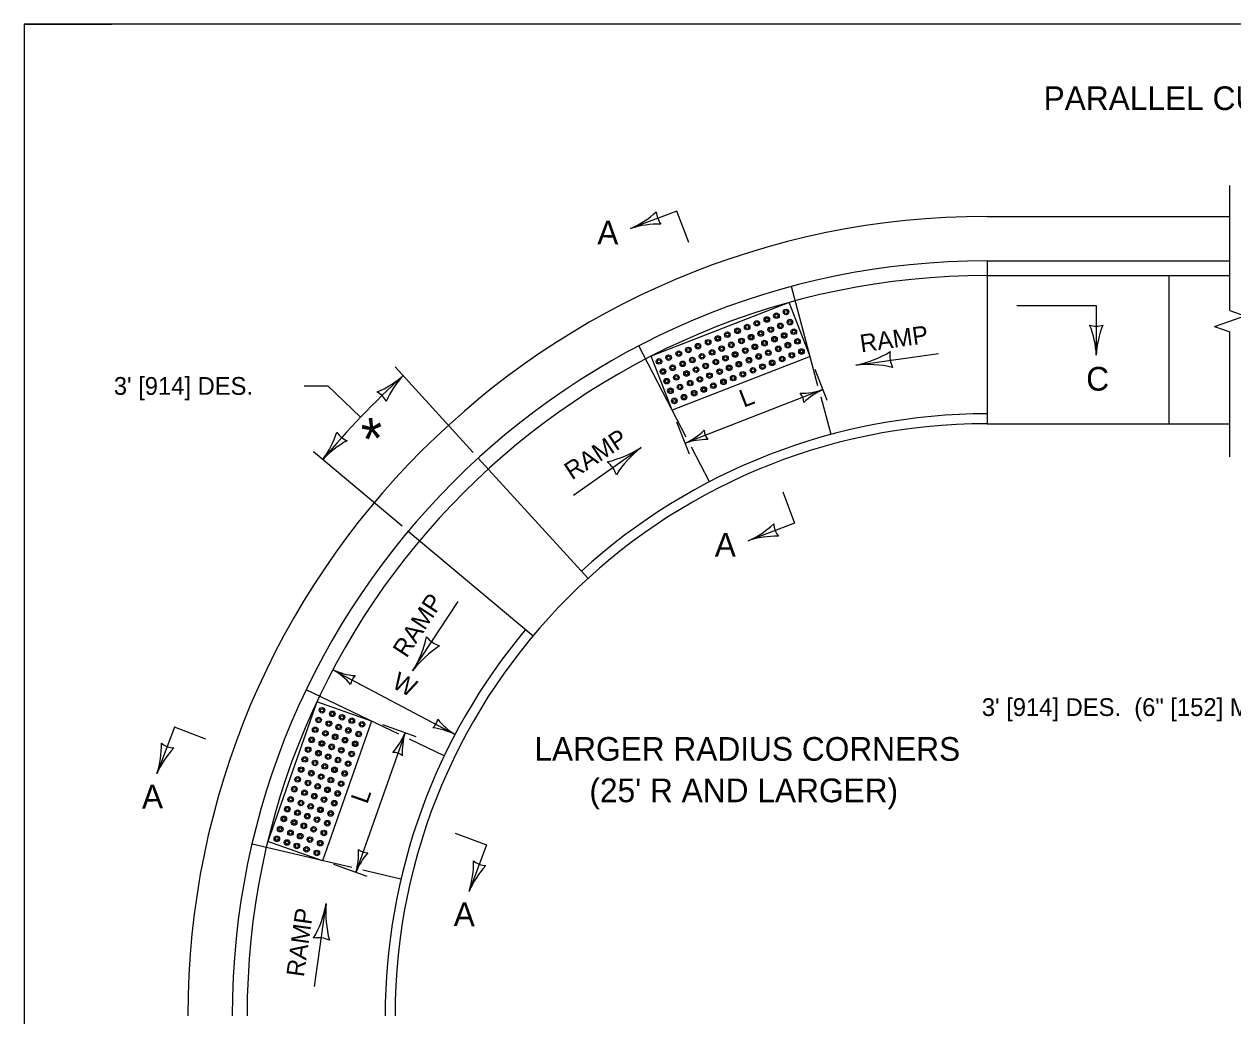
# Model space of a CAD drawing. Extents: x 49991.4 to 50021, y 49987.6 to 50011.4.
# Drawn here: x 50000.336 to 50004.419, y 50007.914 to 50011.263 of the extents above; entities that cross this region are included whole.
import ezdxf

# ---------------------------------------------------------------- set-up
doc = ezdxf.new("R2010")
doc.units = 0
for name, color, linetype in [('Level 1', 7, 'Continuous'), ('Level 2', 7, 'Continuous'), ('Level 3', 7, 'Continuous'), ('Level 6', 7, 'Continuous'), ('Level 8', 7, 'Continuous'), ('P_Dimensions_Styles_Eng', 7, 'Continuous')]:
    doc.layers.add(name, color=color, linetype=linetype)

msp = doc.modelspace()

# ---------------------------------------------------------------- linework, layer by layer
at = {"layer": 'Level 1'}
for p, q in [((50003.5886, 50010.6135), (50004.4081, 50010.6135)), ((50003.5886, 50010.4635), (50004.4081, 50010.4635)), ((50003.5888, 50010.4635), (50003.5888, 50009.9135)), ((50003.5886, 50010.4135), (50004.4081, 50010.4135)), ((50004.2021, 50010.4135), (50004.2021, 50009.9135)), ((50003.0173, 50010.0415), (50002.9275, 50010.3763)), ((50002.5719, 50009.8685), (50002.412, 50010.1759)), ((50002.9909, 50010.1401), (50002.5249, 50009.9589)), ((50003.0614, 50009.8773), (50003.0277, 50010.0027)), ((50003.5886, 50009.9135), (50004.4081, 50009.9135)), ((50001.8698, 50009.7972), (50002.2405, 50009.3909)), ((50002.6504, 50009.7175), (50002.5895, 50009.8346)), ((50001.6332, 50009.5503), (50002.0549, 50009.1973)), ((50001.6013, 50008.8652), (50001.2887, 50009.015)), ((50001.5093, 50008.9093), (50001.3435, 50008.4376)), ((50001.7547, 50008.7918), (50001.6375, 50008.8479)), ((50001.4427, 50008.4144), (50001.1053, 50008.4932)), ((50001.6085, 50008.3757), (50001.4798, 50008.4058))]:
    msp.add_line(p, q, dxfattribs=at)
msp.add_lwpolyline([(50008.6146, 50011.2628), (50000.3356, 50011.2628), (50000.3356, 50000.0624), (50008.6146, 50000.0624)], close=True, dxfattribs=at)
for points in [[(50000.3356, 50011.2628), (50000.3356, 50000.0624)], [(50008.6146, 50011.2628), (50000.3356, 50011.2628)]]:
    msp.add_lwpolyline(points, dxfattribs=at)
for radius, start, end in [(2.7, 89.9972, 179.9963), (2.55, 89.9972, 179.9963), (2.5, 89.9972, 179.9963), (2.0333, 89.9972, 132.3771), (2, 89.9972, 179.9963), (2.0333, 140.0675, 179.9963)]:
    msp.add_arc((50003.5885, 50007.9135), radius, start, end, dxfattribs=at)
at = {"layer": 'Level 2'}
for centre in [(50002.6723, 50010.1218), (50002.7048, 50010.1345), (50002.7373, 50010.1471), (50001.3273, 50008.6885), (50001.3389, 50008.7214), (50001.3157, 50008.6556)]:
    msp.add_circle(centre, 0.00945, dxfattribs=at)
at = {"layer": 'Level 3'}
for p, q in [((50000.3356, 50011.2628), (50000.6313, 50011.2628)), ((50002.9199, 50010.3224), (50002.4539, 50010.1412)), ((50002.9909, 50010.1401), (50002.9199, 50010.3224)), ((50002.5249, 50009.9589), (50002.4539, 50010.1412)), ((50003.0487, 50009.9913), (50003.0079, 50010.0964)), ((50001.362, 50010.041), (50001.4723, 50009.9356)), ((50003.0342, 50010.0285), (50002.5682, 50009.8473)), ((50002.5827, 50009.8101), (50002.5407, 50009.9181)), ((50002.0294, 50009.2186), (50002.0302, 50009.2196)), ((50002.0294, 50009.2186), (50002.0294, 50009.2186)), ((50001.3786, 50009.0823), (50001.7911, 50008.8641)), ((50001.3247, 50008.9742), (50001.1589, 50008.5025)), ((50001.5093, 50008.9093), (50001.3247, 50008.9742)), ((50001.6222, 50008.8696), (50001.4564, 50008.3979)), ((50001.6599, 50008.8564), (50001.547, 50008.8961)), ((50001.3435, 50008.4376), (50001.1589, 50008.5025)), ((50001.4941, 50008.3847), (50001.3812, 50008.4243))]:
    msp.add_line(p, q, dxfattribs=at)
for centre, radius, start, end in [((50002.2683, 50010.8456), 0.2964, 292.9795, 313.163), ((50002.5441, 50010.6329), 0.073, 182.7578, 218.4802), ((50002.479, 50010.2769), 0.3107, 88.5418, 107.7917), ((50003.6613, 50010.133), 0.2964, 2.3605, 22.544), ((50003.9575, 50010.3161), 0.073, 252.1388, 287.8612), ((50004.2678, 50010.1299), 0.3107, 157.9228, 177.1727), ((50003.0737, 50010.4594), 0.3557, 281.5295, 301.713), ((50003.3473, 50010.1436), 0.0876, 171.3078, 207.0302), ((50003.186, 50009.7404), 0.3728, 77.0918, 96.3417), ((50001.4097, 50010.3083), 0.3107, 292.2932, 311.543), ((50001.8315, 50009.8726), 0.2964, 136.7308, 156.9143), ((50001.4935, 50009.9562), 0.073, 26.5091, 62.2315), ((50002.9618, 50010.2387), 0.2223, 268.8315, 289.015), ((50002.9148, 50009.9818), 0.0548, 3.5143, 39.2366), ((50003.1298, 50009.816), 0.233, 114.2028, 133.4526), ((50001.1088, 50009.9726), 0.2964, 322.536, 342.7195), ((50001.4536, 50009.9236), 0.073, 212.3143, 248.0367), ((50002.4714, 50010.0592), 0.233, 294.5668, 313.8166), ((50002.6873, 50009.8948), 0.0548, 183.8783, 219.6007), ((50001.5726, 50009.5818), 0.3107, 118.0983, 137.3482), ((50002.642, 50009.6376), 0.2223, 89.1955, 109.379), ((50002.2205, 50010.1478), 0.3728, 283.1274, 302.3773), ((50002.637, 50009.551), 0.3557, 127.5651, 147.7486), ((50002.2525, 50009.7147), 0.0876, 17.3434, 53.0658), ((50002.6651, 50009.7911), 0.2964, 293.0374, 313.2209), ((50002.941, 50009.5787), 0.073, 182.8157, 218.5381), ((50002.8763, 50009.2226), 0.3107, 88.5998, 107.8496), ((50001.3469, 50009.268), 0.3557, 327.7906, 347.9741), ((50001.7643, 50009.2473), 0.0876, 217.5689, 253.2913), ((50001.944, 50008.852), 0.3728, 123.3529, 142.6028), ((50001.269, 50008.8888), 0.2223, 40.3043, 60.4878), ((50001.4745, 50009.2946), 0.233, 245.6756, 264.9254), ((50001.4926, 50009.0238), 0.0548, 134.9871, 170.7094), ((50001.6788, 50008.9259), 0.0548, 313.3208, 349.0431), ((50001.9062, 50009.0543), 0.2223, 218.638, 238.8215), ((50001.4155, 50008.9515), 0.2223, 318.2162, 338.3997), ((50001.8457, 50008.8038), 0.233, 163.5875, 182.8373), ((50001.689, 50008.6547), 0.233, 64.0093, 83.2591), ((50000.5028, 50008.8248), 0.2964, 341.6596, 1.8431), ((50001.069, 50008.6075), 0.3107, 137.2219, 156.4718), ((50000.8446, 50008.8914), 0.073, 231.4379, 267.1603), ((50001.5799, 50008.7486), 0.0548, 52.899, 88.6213), ((50001.2325, 50008.4623), 0.233, 343.9515, 3.2013), ((50001.6636, 50008.3174), 0.2223, 138.5802, 158.7637), ((50001.4979, 50008.5192), 0.0548, 233.263, 268.9854), ((50001.5571, 50008.427), 0.2964, 341.7175, 1.901), ((50002.1235, 50008.2102), 0.3107, 137.2799, 156.5297), ((50001.8988, 50008.4939), 0.073, 231.4958, 267.2182), ((50000.9894, 50008.36), 0.3728, 330.3982, 349.648), ((50001.7104, 50008.261), 0.3557, 174.8358, 195.0193), ((50001.3293, 50008.0897), 0.0876, 64.6141, 100.3365)]:
    msp.add_arc(centre, radius, start, end, dxfattribs=at)
at = {"layer": 'Level 6'}
for p, q in [((50004.4081, 50010.296), (50004.4081, 50010.7183)), ((50002.541, 50010.6318), (50002.3841, 50010.5727)), ((50002.5809, 50010.5259), (50002.541, 50010.6318)), ((50003.6888, 50010.3129), (50003.872, 50010.3129)), ((50003.7743, 50010.3129), (50003.9575, 50010.3129)), ((50003.9575, 50010.3129), (50003.9575, 50010.1452)), ((50003.9575, 50010.3129), (50003.9575, 50010.1452)), ((50004.4081, 50010.296), (50004.4589, 50010.2778)), ((50004.3571, 50010.2417), (50004.4081, 50010.2598)), ((50004.4081, 50010.2598), (50004.4589, 50010.2778)), ((50004.3571, 50010.2417), (50004.4081, 50010.2237)), ((50004.4081, 50009.8014), (50004.4081, 50010.2237)), ((50003.1448, 50010.1109), (50003.4249, 50010.1507)), ((50002.1914, 50009.6724), (50002.4201, 50009.833)), ((50002.898, 50009.6836), (50002.938, 50009.5776)), ((50002.938, 50009.5776), (50002.7811, 50009.5183)), ((50001.6478, 50009.0784), (50001.8014, 50009.313)), ((50000.8434, 50008.8884), (50000.7841, 50008.7315)), ((50000.9493, 50008.8485), (50000.8434, 50008.8884)), ((50001.7916, 50008.5309), (50001.8976, 50008.491)), ((50001.8976, 50008.491), (50001.8385, 50008.334)), ((50001.3164, 50008.013), (50001.3561, 50008.2931))]:
    msp.add_line(p, q, dxfattribs=at)
at = {"layer": 'Level 8'}
for centre, radius in [((50002.877, 50010.2782), 0.00945), ((50002.9095, 50010.2908), 0.00945), ((50002.9095, 50010.2908), 0.00525), ((50002.7781, 50010.2399), 0.00945), ((50002.7781, 50010.2399), 0.00525), ((50002.8106, 50010.2525), 0.00945), ((50002.8106, 50010.2525), 0.00525), ((50002.8445, 50010.2655), 0.00945), ((50002.8445, 50010.2655), 0.00525), ((50002.877, 50010.2782), 0.00525), ((50002.8903, 50010.2439), 0.00945), ((50002.8903, 50010.2439), 0.00525), ((50002.9229, 50010.2566), 0.00945), ((50002.9229, 50010.2566), 0.00525), ((50002.6788, 50010.2013), 0.00945), ((50002.6788, 50010.2013), 0.00525), ((50002.7113, 50010.2139), 0.00945), ((50002.7113, 50010.2139), 0.00525), ((50002.7456, 50010.2272), 0.00945), ((50002.7456, 50010.2272), 0.00525), ((50002.7914, 50010.2056), 0.00945), ((50002.7914, 50010.2056), 0.00525), ((50002.824, 50010.2183), 0.00945), ((50002.824, 50010.2183), 0.00525), ((50002.8578, 50010.2313), 0.00945), ((50002.8578, 50010.2313), 0.00525), ((50002.8705, 50010.1988), 0.00945), ((50002.8705, 50010.1988), 0.00525), ((50002.903, 50010.2114), 0.00945), ((50002.903, 50010.2114), 0.00525), ((50002.9355, 50010.2241), 0.00945), ((50002.9355, 50010.2241), 0.00525), ((50002.5795, 50010.1626), 0.00945), ((50002.5795, 50010.1626), 0.00525), ((50002.6121, 50010.1753), 0.00945), ((50002.6121, 50010.1753), 0.00525), ((50002.6464, 50010.1885), 0.00945), ((50002.6464, 50010.1885), 0.00525), ((50002.6596, 50010.1544), 0.00945), ((50002.6921, 50010.167), 0.00945), ((50002.6921, 50010.167), 0.00525), ((50002.7247, 50010.1796), 0.00945), ((50002.7247, 50010.1796), 0.00525), ((50002.7589, 50010.193), 0.00945), ((50002.7589, 50010.193), 0.00525), ((50002.7716, 50010.1604), 0.00945), ((50002.7716, 50010.1604), 0.00525), ((50002.8041, 50010.1731), 0.00945), ((50002.8041, 50010.1731), 0.00525), ((50002.8366, 50010.1857), 0.00945), ((50002.8366, 50010.1857), 0.00525), ((50002.8493, 50010.1532), 0.00945), ((50002.8831, 50010.1662), 0.00945), ((50002.8831, 50010.1662), 0.00525), ((50002.9156, 50010.1789), 0.00945), ((50002.9156, 50010.1789), 0.00525), ((50002.9482, 50010.1915), 0.00945), ((50002.9482, 50010.1915), 0.00525), ((50002.9615, 50010.1573), 0.00945), ((50002.4802, 50010.124), 0.00945), ((50002.4802, 50010.124), 0.00525), ((50002.5128, 50010.1367), 0.00945), ((50002.5128, 50010.1367), 0.00525), ((50002.547, 50010.15), 0.00945), ((50002.547, 50010.15), 0.00525), ((50002.5603, 50010.1157), 0.00945), ((50002.5929, 50010.1284), 0.00945), ((50002.5929, 50010.1284), 0.00525), ((50002.6254, 50010.141), 0.00945), ((50002.6254, 50010.141), 0.00525), ((50002.6596, 50010.1544), 0.00525), ((50002.6723, 50010.1218), 0.00525), ((50002.7048, 50010.1345), 0.00525), ((50002.7373, 50010.1471), 0.00525), ((50002.75, 50010.1146), 0.00945), ((50002.7842, 50010.1279), 0.00945), ((50002.7842, 50010.1279), 0.00525), ((50002.8167, 50010.1406), 0.00945), ((50002.8167, 50010.1406), 0.00525), ((50002.8493, 50010.1532), 0.00525), ((50002.8626, 50010.119), 0.00945), ((50002.8626, 50010.119), 0.00525), ((50002.8964, 50010.132), 0.00945), ((50002.8964, 50010.132), 0.00525), ((50002.929, 50010.1446), 0.00945), ((50002.929, 50010.1446), 0.00525), ((50002.9615, 50010.1573), 0.00525), ((50002.4936, 50010.0898), 0.00945), ((50002.4936, 50010.0898), 0.00525), ((50002.5261, 50010.1024), 0.00945), ((50002.5261, 50010.1024), 0.00525), ((50002.5603, 50010.1157), 0.00525), ((50002.573, 50010.0832), 0.00945), ((50002.573, 50010.0832), 0.00525), ((50002.6055, 50010.0959), 0.00945), ((50002.6055, 50010.0959), 0.00525), ((50002.638, 50010.1085), 0.00945), ((50002.638, 50010.1085), 0.00525), ((50002.6507, 50010.076), 0.00945), ((50002.6507, 50010.076), 0.00525), ((50002.6849, 50010.0893), 0.00945), ((50002.6849, 50010.0893), 0.00525), ((50002.7174, 50010.102), 0.00945), ((50002.7174, 50010.102), 0.00525), ((50002.75, 50010.1146), 0.00525), ((50002.7633, 50010.0804), 0.00945), ((50002.7633, 50010.0804), 0.00525), ((50002.7975, 50010.0937), 0.00945), ((50002.7975, 50010.0937), 0.00525), ((50002.8301, 50010.1063), 0.00945), ((50002.8301, 50010.1063), 0.00525), ((50002.5062, 50010.0572), 0.00945), ((50002.5062, 50010.0572), 0.00525), ((50002.5387, 50010.0699), 0.00945), ((50002.5387, 50010.0699), 0.00525), ((50002.5514, 50010.0374), 0.00945), ((50002.5514, 50010.0374), 0.00525), ((50002.5856, 50010.0507), 0.00945), ((50002.5856, 50010.0507), 0.00525), ((50002.6181, 50010.0633), 0.00945), ((50002.6181, 50010.0633), 0.00525), ((50002.664, 50010.0417), 0.00945), ((50002.664, 50010.0417), 0.00525), ((50002.6982, 50010.0551), 0.00945), ((50002.6982, 50010.0551), 0.00525), ((50002.7308, 50010.0677), 0.00945), ((50002.7308, 50010.0677), 0.00525), ((50002.5189, 50010.0247), 0.00945), ((50002.5189, 50010.0247), 0.00525), ((50002.5322, 50009.9905), 0.00945), ((50002.5647, 50010.0031), 0.00945), ((50002.5647, 50010.0031), 0.00525), ((50002.5989, 50010.0164), 0.00945), ((50002.5989, 50010.0164), 0.00525), ((50002.6315, 50010.0291), 0.00945), ((50002.6315, 50010.0291), 0.00525), ((50002.5322, 50009.9905), 0.00525), ((50001.3419, 50008.9457), 0.00945), ((50001.3419, 50008.9457), 0.00525), ((50001.3766, 50008.9335), 0.00945), ((50001.3766, 50008.9335), 0.00525), ((50001.3303, 50008.9128), 0.00945), ((50001.3303, 50008.9128), 0.00525), ((50001.365, 50008.9006), 0.00945), ((50001.365, 50008.9006), 0.00525), ((50001.3979, 50008.889), 0.00945), ((50001.4095, 50008.922), 0.00945), ((50001.4095, 50008.922), 0.00525), ((50001.4424, 50008.9104), 0.00945), ((50001.4424, 50008.9104), 0.00525), ((50001.4771, 50008.8982), 0.00945), ((50001.4771, 50008.8982), 0.00525), ((50001.3188, 50008.8799), 0.00945), ((50001.3188, 50008.8799), 0.00525), ((50001.3534, 50008.8677), 0.00945), ((50001.3534, 50008.8677), 0.00525), ((50001.3863, 50008.8561), 0.00945), ((50001.3863, 50008.8561), 0.00525), ((50001.3979, 50008.889), 0.00525), ((50001.4308, 50008.8775), 0.00945), ((50001.4308, 50008.8775), 0.00525), ((50001.4655, 50008.8653), 0.00945), ((50001.4655, 50008.8653), 0.00525), ((50001.295, 50008.8128), 0.00945), ((50001.295, 50008.8128), 0.00525), ((50001.3066, 50008.8457), 0.00945), ((50001.3066, 50008.8457), 0.00525), ((50001.3413, 50008.8335), 0.00945), ((50001.3413, 50008.8335), 0.00525), ((50001.3742, 50008.8219), 0.00945), ((50001.3742, 50008.8219), 0.00525), ((50001.4071, 50008.8104), 0.00945), ((50001.4071, 50008.8104), 0.00525), ((50001.4193, 50008.8446), 0.00945), ((50001.4193, 50008.8446), 0.00525), ((50001.4539, 50008.8324), 0.00945), ((50001.4539, 50008.8324), 0.00525), ((50001.2835, 50008.7798), 0.00945), ((50001.2835, 50008.7798), 0.00525), ((50001.3181, 50008.7677), 0.00945), ((50001.3297, 50008.8006), 0.00945), ((50001.3297, 50008.8006), 0.00525), ((50001.3626, 50008.789), 0.00945), ((50001.3626, 50008.789), 0.00525), ((50001.3955, 50008.7774), 0.00945), ((50001.3955, 50008.7774), 0.00525), ((50001.4302, 50008.7653), 0.00945), ((50001.4418, 50008.7982), 0.00945), ((50001.4418, 50008.7982), 0.00525), ((50001.2713, 50008.7452), 0.00945), ((50001.2713, 50008.7452), 0.00525), ((50001.3059, 50008.733), 0.00945), ((50001.3059, 50008.733), 0.00525), ((50001.3181, 50008.7677), 0.00525), ((50001.3511, 50008.7561), 0.00945), ((50001.3511, 50008.7561), 0.00525), ((50001.384, 50008.7445), 0.00945), ((50001.384, 50008.7445), 0.00525), ((50001.4186, 50008.7323), 0.00945), ((50001.4186, 50008.7323), 0.00525), ((50001.4302, 50008.7653), 0.00525), ((50001.2597, 50008.7123), 0.00945), ((50001.2597, 50008.7123), 0.00525), ((50001.2944, 50008.7001), 0.00945), ((50001.2944, 50008.7001), 0.00525), ((50001.3273, 50008.6885), 0.00525), ((50001.3389, 50008.7214), 0.00525), ((50001.3718, 50008.7099), 0.00945), ((50001.3718, 50008.7099), 0.00525), ((50001.4065, 50008.6977), 0.00945), ((50001.4065, 50008.6977), 0.00525), ((50001.236, 50008.6447), 0.00945), ((50001.2483, 50008.6794), 0.00945), ((50001.2483, 50008.6794), 0.00525), ((50001.2828, 50008.6672), 0.00945), ((50001.2828, 50008.6672), 0.00525), ((50001.3157, 50008.6556), 0.00525), ((50001.3486, 50008.644), 0.00945), ((50001.3602, 50008.6769), 0.00945), ((50001.3602, 50008.6769), 0.00525), ((50001.3949, 50008.6647), 0.00945), ((50001.3949, 50008.6647), 0.00525), ((50001.2244, 50008.6117), 0.00945), ((50001.2244, 50008.6117), 0.00525), ((50001.236, 50008.6447), 0.00525), ((50001.2706, 50008.6325), 0.00945), ((50001.2706, 50008.6325), 0.00525), ((50001.3035, 50008.6209), 0.00945), ((50001.3035, 50008.6209), 0.00525), ((50001.3365, 50008.6093), 0.00945), ((50001.3365, 50008.6093), 0.00525), ((50001.3486, 50008.644), 0.00525), ((50001.3833, 50008.6318), 0.00945), ((50001.3833, 50008.6318), 0.00525), ((50001.2128, 50008.5788), 0.00945), ((50001.2128, 50008.5788), 0.00525), ((50001.2475, 50008.5666), 0.00945), ((50001.2475, 50008.5666), 0.00525), ((50001.2591, 50008.5996), 0.00945), ((50001.2591, 50008.5996), 0.00525), ((50001.292, 50008.588), 0.00945), ((50001.292, 50008.588), 0.00525), ((50001.3249, 50008.5764), 0.00945), ((50001.3249, 50008.5764), 0.00525), ((50001.3596, 50008.5642), 0.00945), ((50001.3711, 50008.5972), 0.00945), ((50001.3711, 50008.5972), 0.00525), ((50001.2006, 50008.5442), 0.00945), ((50001.2006, 50008.5442), 0.00525), ((50001.2353, 50008.532), 0.00945), ((50001.2353, 50008.532), 0.00525), ((50001.2682, 50008.5204), 0.00945), ((50001.2804, 50008.5551), 0.00945), ((50001.2804, 50008.5551), 0.00525), ((50001.3133, 50008.5435), 0.00945), ((50001.3133, 50008.5435), 0.00525), ((50001.348, 50008.5313), 0.00945), ((50001.348, 50008.5313), 0.00525), ((50001.3596, 50008.5642), 0.00525), ((50001.1891, 50008.5112), 0.00945), ((50001.1891, 50008.5112), 0.00525), ((50001.2237, 50008.4991), 0.00945), ((50001.2237, 50008.4991), 0.00525), ((50001.2566, 50008.4875), 0.00945), ((50001.2566, 50008.4875), 0.00525), ((50001.2682, 50008.5204), 0.00525), ((50001.3011, 50008.5088), 0.00945), ((50001.3011, 50008.5088), 0.00525), ((50001.3358, 50008.4966), 0.00945), ((50001.3358, 50008.4966), 0.00525), ((50001.2896, 50008.4759), 0.00945), ((50001.2896, 50008.4759), 0.00525), ((50001.3242, 50008.4637), 0.00945), ((50001.3242, 50008.4637), 0.00525)]:
    msp.add_circle(centre, radius, dxfattribs=at)
at = {"layer": 'P_Dimensions_Styles_Eng'}
for p, q in [((50001.852, 50009.8167), (50001.5887, 50010.1053)), ((50001.282, 50010.041), (50001.362, 50010.041)), ((50001.6125, 50009.5676), (50001.3134, 50009.818))]:
    msp.add_line(p, q, dxfattribs=at)
msp.add_arc((50003.5885, 50007.9135), 2.927, 132.3771, 140.0675, dxfattribs=at)

# ---------------------------------------------------------------- texts
at = {"layer": 'Level 2'}
for s, p in [('PARALLEL CURB RAMPS', (50003.7794, 50010.9728)), ('C', (50003.9235, 50010.0252)), ('LARGER RADIUS CORNERS', (50002.0592, 50008.7751)), ("(25' R AND LARGER)", (50002.245, 50008.6351))]:
    msp.add_text(s, height=0.08, dxfattribs=at).set_placement(p)
for s, height, rotation, p in [('A', 0.08, 359.5801, (50002.2716, 50010.5192)), ('RAMP', 0.06, 8.0735, (50003.1635, 50010.154)), ('L', 0.06, 21.2006, (50002.7664, 50009.9673)), ('RAMP', 0.06, 33.3283, (50002.1861, 50009.7219)), ('A', 0.08, 359.5801, (50002.6686, 50009.4647)), ('RAMP', 0.06, 56.9027, (50001.6273, 50009.1196)), ('W', 0.06, 332.1915, (50001.5741, 50009.0241)), ('A', 0.08, 0.7945, (50000.7337, 50008.6136)), ('L', 0.06, 70.5853, (50001.4943, 50008.6265)), ('A', 0.08, 359.5801, (50001.7865, 50008.2168)), ('RAMP', 0.06, 81.9381, (50001.2802, 50008.0429))]:
    msp.add_text(s, height=height, rotation=rotation, dxfattribs=at).set_placement(p)
at = {"layer": 'Level 3'}
msp.add_text('*', height=0.14, rotation=7.3766, dxfattribs=at).set_placement((50001.4869, 50009.7891))
at = {"layer": 'P_Dimensions_Styles_Eng'}
for s, p in [("3' [914] DES.", (50000.6385, 50010.011)), ('3\' [914] DES.  (6" [152] MIN.)', (50003.5709, 50008.9263))]:
    msp.add_text(s, height=0.06, dxfattribs=at).set_placement(p)

doc.saveas('drawing.dxf')
